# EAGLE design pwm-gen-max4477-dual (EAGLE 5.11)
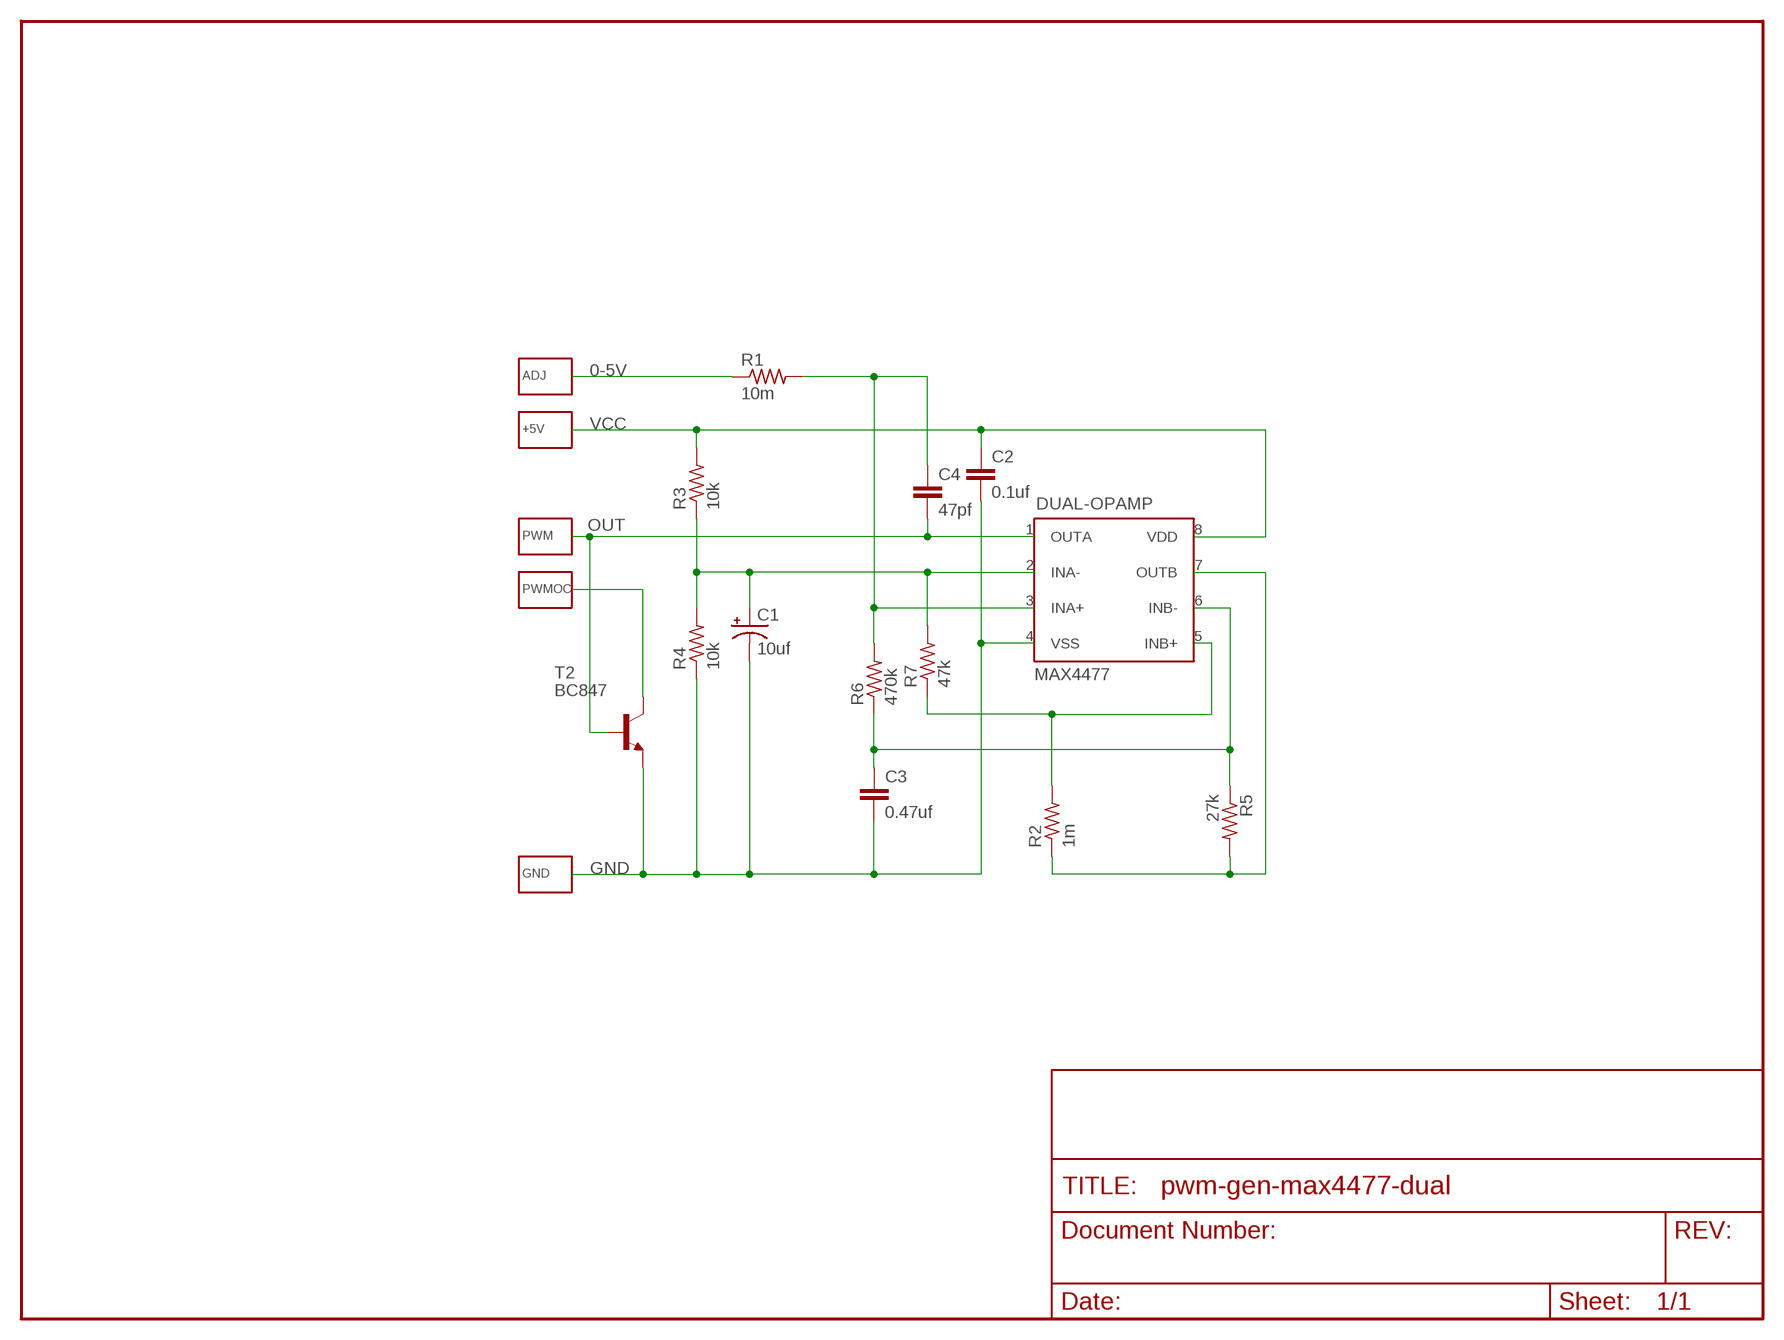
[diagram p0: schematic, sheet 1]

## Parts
+5V  WIREPAD-SMD-NO-VALUE  [WIREPAD-SMD]
ADJ  WIREPAD-SMD-NO-VALUE  [WIREPAD-SMD]
C1  10uf  CPOL-USD  [PANASONIC_D]
C2  0.1uf  C-EUC0805  [C0805]
C3  0.47uf  C-EUC1206  [C1206]
C4  47pf  C-EUC0805  [C0805]
DUAL-OPAMP  MAX4477  [UMAX8]
GND  WIREPAD-SMD-NO-VALUE  [WIREPAD-SMD]
PWM  WIREPAD-SMD-NO-VALUE  [WIREPAD-SMD]
PWMOC  WIREPAD-SMD-NO-VALUE  [WIREPAD-SMD]
R1  10m  R-US_R0805  [R0805]
R2  1m  R-US_M0805  [M0805]
R3  10k  R-US_M0805  [M0805]
R4  10k  R-US_M0805  [M0805]
R5  27k  R-US_M0805  [M0805]
R6  470k  R-US_M0805  [M0805]
R7  47k  R-US_M1206  [M1206]
T2  BC847  [SOT23]

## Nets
0-5V: ADJ.1(P) R1.1
GND: C1.- C2.2 C3.2 DUAL-OPAMP.4(VSS) GND.1(P) R4.1 T2.2(E)
N$2: DUAL-OPAMP.5(INB+) R2.2 R7.1
N$3: C4.1 DUAL-OPAMP.3(INA+) R1.2 R6.2
N$4: C3.1 DUAL-OPAMP.6(INB-) R5.1 R6.1
N$6: C1.+ DUAL-OPAMP.2(INA-) R3.1 R4.2 R7.2
N$7: PWMOC.1(P) T2.3(C)
N$8: DUAL-OPAMP.7(OUTB) R2.1 R5.2
OUT: C4.2 DUAL-OPAMP.1(OUTA) PWM.1(P) T2.1(B)
VCC: +5V.1(P) C2.1 DUAL-OPAMP.8(VDD) R3.2

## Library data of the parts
+5V ADJ GND PWM PWMOC = trl:WIREPAD-SMD-NO-VALUE
C1 = resistor:CPOL-US: POLARIZED CAPACITOR, American symbol
C2-C4 = rcl:C-EU: CAPACITOR, European symbol
DUAL-OPAMP = trl:MAX4477
R1 R6 R7 = resistor:R-US_: RESISTOR, American symbol
R2-R5 = rcl:R-US_: RESISTOR, American symbol
T2 = transistor-neu-to92:BC847: NPN TRANSISTOR

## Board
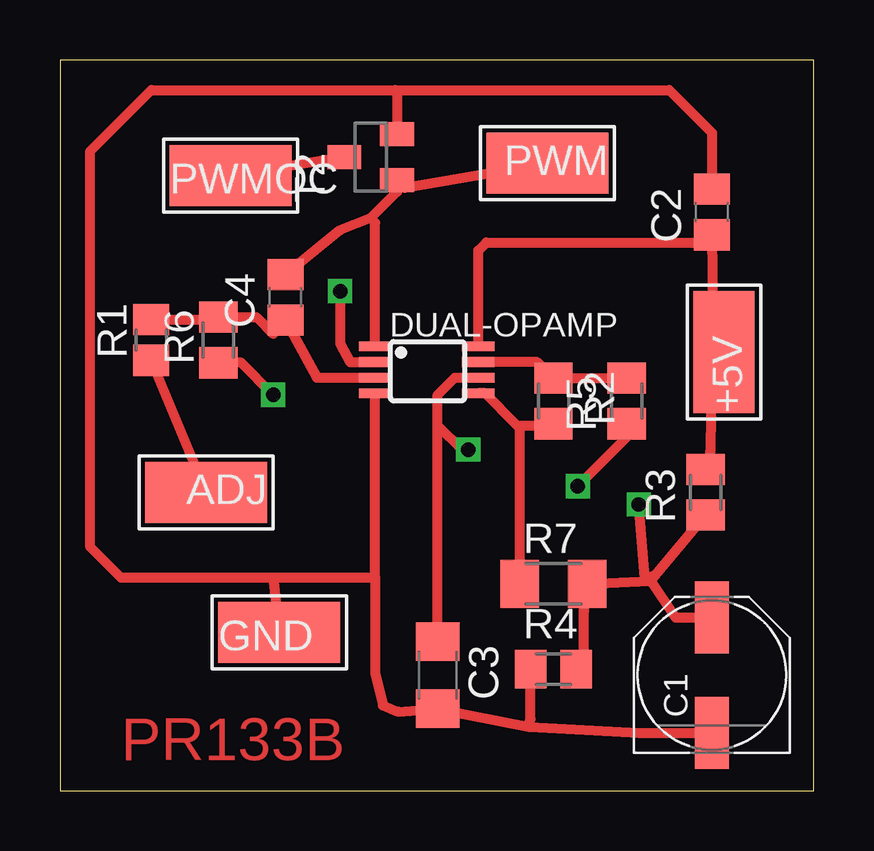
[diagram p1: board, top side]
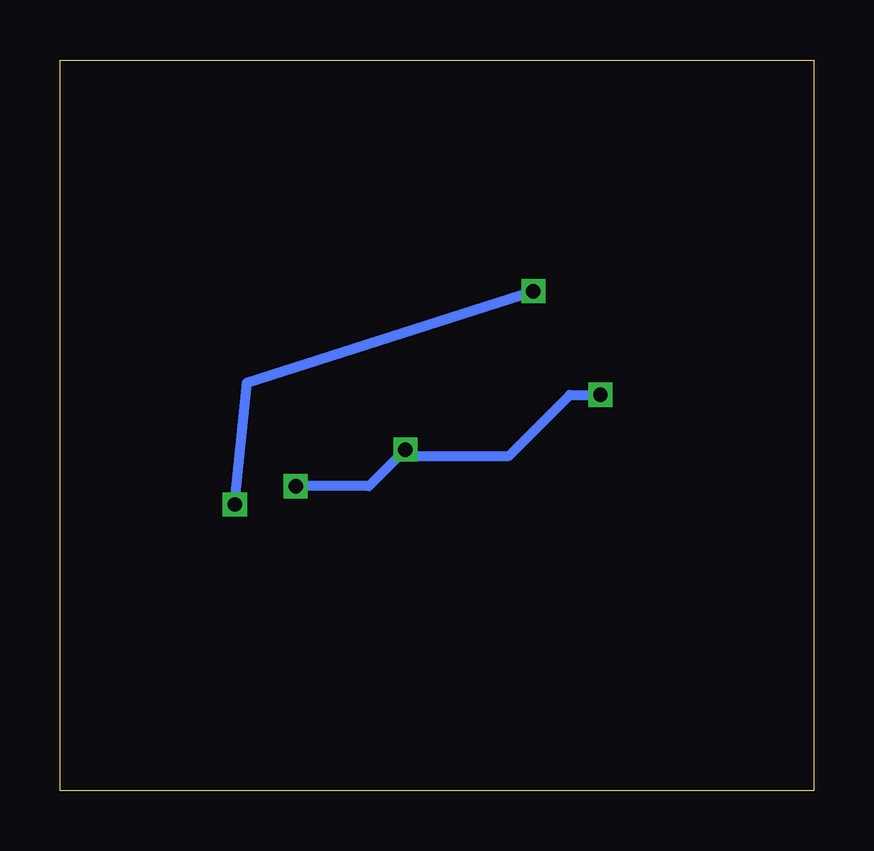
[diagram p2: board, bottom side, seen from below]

Size 31.42 x 30.47 mm. Coordinates in mm from the lower left corner, seen from the top.
Outline: 0,0 31.42,0 31.42,30.47 0,30.47 0,0
Copper layers (1*16): Top 0.035mm / dielectric 1.5mm / Bottom 0.035mm
Design rules "default": minimum track width 10mil, minimum drill 24mil, track to track 8mil, track to pad 8mil, pad to pad 8mil, via to via 8mil, smd to smd 8mil, copper to edge 40mil, drill to drill 8mil, minimum pad ring 10mil, minimum via ring 8mil, stop-mask expansion 4mil, vias tented up to drill 0mil, thermal gap 10mil

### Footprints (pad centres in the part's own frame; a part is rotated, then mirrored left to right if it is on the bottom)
WIREPAD-SMD = smd 2.54 x 5.08: 1 0,0
PANASONIC_D = smd 3 x 1.4: + 2.4,0; - -2.4,0
C0805 = smd 1.3 x 1.5: 1 -0.95,0; 2 0.95,0
C1206 = smd 1.6 x 1.8: 1 -1.4,0; 2 1.4,0
UMAX8 = smd 1.35 x 0.4: 1 -2.35,1; 2 -2.35,0.35; 3 -2.35,-0.3; 4 -2.35,-0.95; 5 1.95,-0.95; 6 1.95,-0.3; 7 1.95,0.35; 8 1.95,1
R0805 = smd 1.3 x 1.5: 1 -0.85,0; 2 0.85,0
M0805 = smd 1.3 x 1.6: 1 -0.95,0; 2 0.95,0
M1206 = smd 1.6 x 2: 1 -1.4,0; 2 1.4,0
SOT23 = smd 1 x 1.4: 1 -0.95,-1.1; 2 0.95,-1.1; 3 0,1.1

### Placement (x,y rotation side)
+5V  27.69,18.29 0 top
ADJ  6.1,12.45 90 top
C1  27.18,4.83 90 top
C2  27.18,24.13 90 top
C3  15.75,4.83 270 top
C4  9.4,20.57 90 top
DUAL-OPAMP  15.49,17.53 0 top
GND  9.14,6.6 270 top
PWM  20.32,26.16 90 top
PWMOC  7.11,25.65 270 top
R1  3.81,18.8 90 top
R2  20.57,16.26 270 top
R3  26.92,12.45 90 top
R4  20.57,5.08 0 top
R5  23.62,16.26 90 top
R6  6.6,18.8 90 top
R7  20.57,8.64 0 top
T2  12.95,26.42 90 top

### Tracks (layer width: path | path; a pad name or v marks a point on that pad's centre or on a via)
0-5V
  Top 0.406: R1.1 ADJ.1
GND
  Top 0.406: 19.56,2.66 C3.2 14.09,3.3 13.46,3.56 13.14,4.89 13.14,8.89 | 19.56,2.66 24.15,2.41 C1.- | R4.1 19.62,2.98 19.56,2.66 | 13.14,8.89 DUAL-OPAMP.4 | C2.2 27.18,27.43 25.4,29.21 13.97,29.21 | 13.97,29.21 3.81,29.21 1.27,26.67 1.27,10.16 2.54,8.89 8.89,8.89 | 8.89,8.89 GND.1 | 8.89,8.89 13.14,8.89 | T2.2 14.05,29.13 13.97,29.21
N$2
  Top 0.406: DUAL-OPAMP.5 17.71,16.58 19.05,15.24 | 19.05,15.24 20.51,15.24 R2.2 | R7.1 19.17,15.12 19.05,15.24
N$3
  Top 0.406: DUAL-OPAMP.3 10.71,17.23 C4.1 8.89,19.12 8.89,19.05 8.19,19.75 R6.2 6.5,19.65 R1.2
N$4  (via drill 0.6)
  Top 0.406: DUAL-OPAMP.6 16.46,17.23 15.75,16.51 15.75,15.24 | C3.1 15.75,15.24 | R6.1 7.55,17.85 v8.89,16.51 | v17.02,14.22 16.76,14.22 15.75,15.24 | R5.1 23.62,14.73 v21.59,12.7
  Bottom 0.406: v8.89,16.51 10.16,16.51 12.7,13.97 16.76,13.97 v17.02,14.22 18.54,12.7 v21.59,12.7
N$6  (via drill 0.6)
  Top 0.406: 24.64,8.76 24.81,8.96 | 24.81,8.96 R3.1 | 24.64,8.76 R7.2 21.84,7.5 21.84,5.84 21.78,5.52 R4.2 | C1.+ 25.66,7.23 24.64,8.76 | DUAL-OPAMP.2 12.1,17.88 11.68,18.64 v11.68,20.83 | v24.13,11.94 24.38,8.88 24.81,8.96
  Bottom 0.406: v11.68,20.83 23.62,17.02 v24.13,11.94
N$7
  Top 0.406: T2.3 PWMOC.1
N$8
  Top 0.406: DUAL-OPAMP.7 19.9,17.88 R2.1 R5.2
OUT
  Top 0.406: PWM.1 14.37,25.15 T2.1 14.05,24.98 12.95,23.88 | 12.95,23.88 11.68,23.37 C4.2 | DUAL-OPAMP.1 13.14,23.69 12.95,23.88
VCC
  Top 0.406: 27.69,19.05 +5V.1 | 27.69,19.05 26.92,18.8 27.18,18.8 | 27.18,18.8 27.24,18.29 C2.1 26.86,22.86 17.78,22.86 17.44,22.52 DUAL-OPAMP.8 | R3.2 27.11,14.16 27.18,18.8 | 27.18,18.8 27.69,19.05

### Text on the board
Top: PR133B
